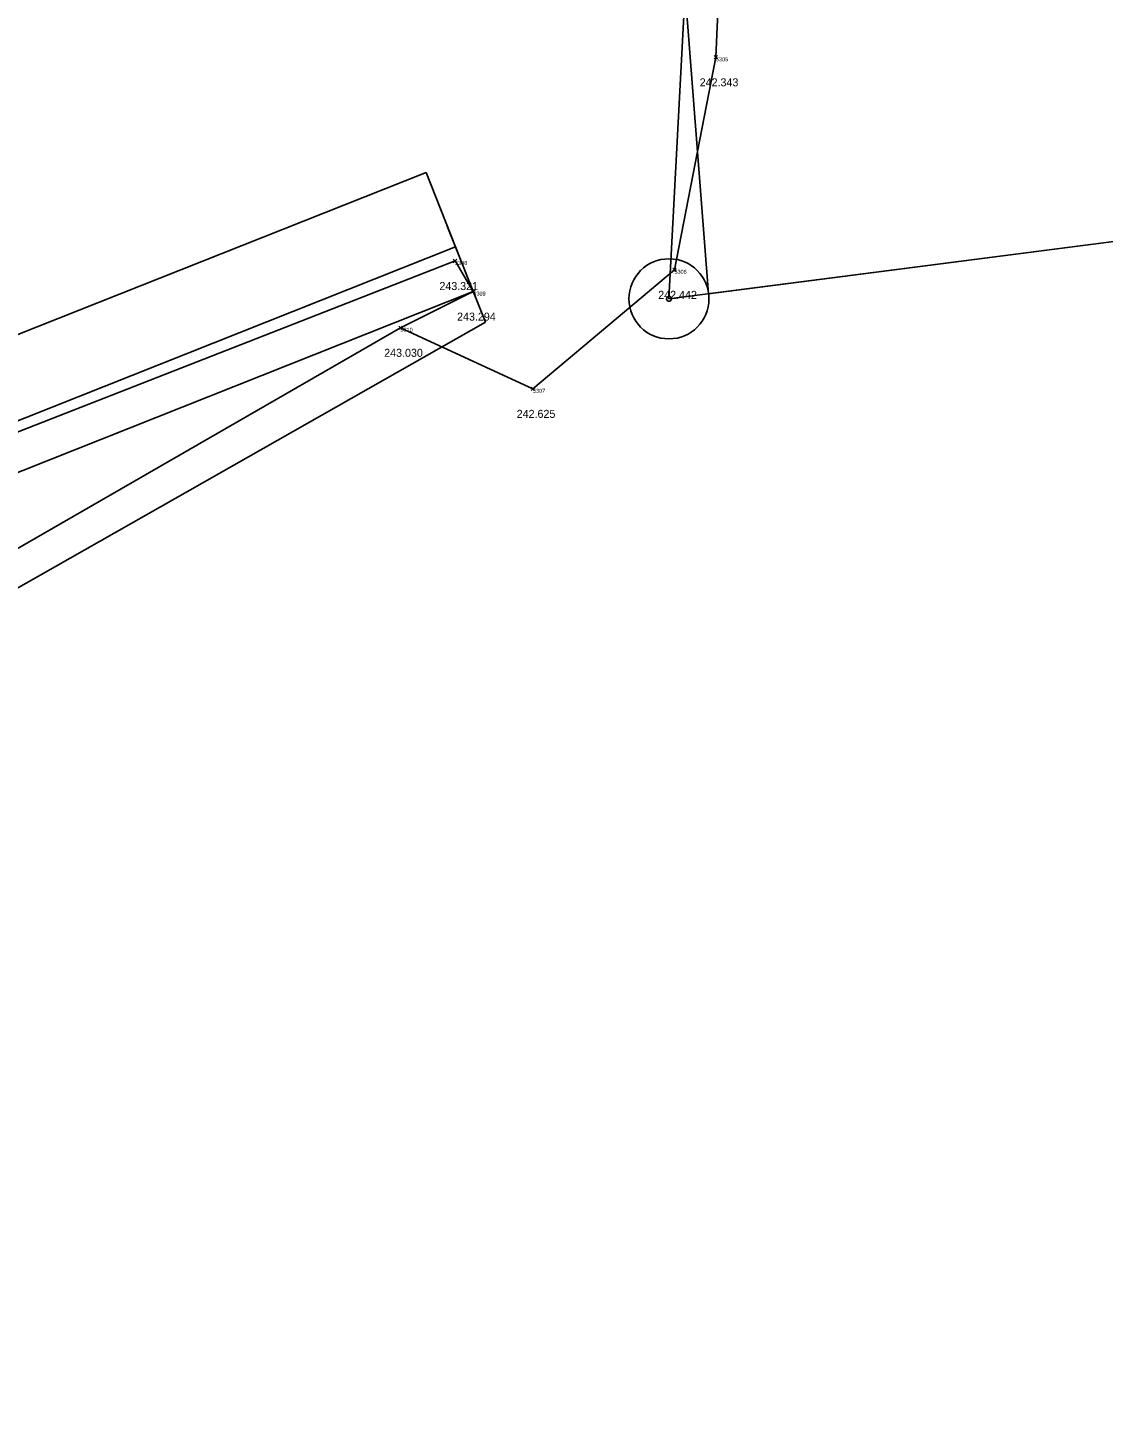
# Model space of a CAD drawing. Extents: x -809973 to -809318, y -1011363 to -1010505.
# Drawn here: x -809857.01 to -809843.56, y -1010848.32 to -1010831.13 of the extents above; entities that cross this region are included whole.
import ezdxf

# ---------------------------------------------------------------- set-up
doc = ezdxf.new("R2010")
doc.units = 0
for name, color, linetype in [('18b - zaměření - čísla bodů', 7, 'Continuous'), ('18c - zaměření - výšky', 7, 'Continuous'), ('19a - katastr hranice', 7, 'Continuous'), ('19b - katastr SŽDC', 7, 'Continuous'), ('26 - obvod_stavby', 7, 'Continuous'), ('SO_02', 7, 'Continuous'), ('stav_stav', 7, 'Continuous')]:
    doc.layers.add(name, color=color, linetype=linetype)

# ---------------------------------------------------------------- blocks, each defined once
blk = doc.blocks.new('POINT_DISPLAY')
for p, q in [((-0.021, -0.021), (0.021, 0.021)), ((-0.021, 0.021), (0.021, -0.021))]:
    blk.add_line(p, q)

msp = doc.modelspace()

# ---------------------------------------------------------------- linework, layer by layer
at = {"layer": '19a - katastr hranice'}
for radius in [0.5, 0.0303]:
    msp.add_circle((-809848.99, -1010834.52), radius, dxfattribs=at)
at = {"layer": '19b - katastr SŽDC'}
msp.add_lwpolyline([(-809854.75, -1010785.76), (-809847.8, -1010811.91), (-809848.47, -1010824.63), (-809848.99, -1010834.52), (-809828.94, -1010831.94), (-809811.76, -1010846.11), (-809806.99, -1010849.89), (-809798.33, -1010856.76), (-809803.49, -1010861.61), (-809820.27, -1010877.38), (-809819.54, -1010907.65), (-809817.34, -1010954.54), (-809819.55, -1010971.19), (-809826.87, -1010981.55), (-809825.08, -1010988.69), (-809823.59, -1010994.66), (-809817.83, -1011024.91), (-809805.06, -1011048.21), (-809777.13, -1011090.84), (-809773.31, -1011095.41), (-809752.3, -1011120.38), (-809722.41, -1011150.52), (-809685.06, -1011180.11)], dxfattribs=at)
at = {"layer": '26 - obvod_stavby'}
msp.add_lwpolyline([(-809819.539, -1010907.68), (-809820.27, -1010877.38), (-809829.436, -1010832.004), (-809848.494, -1010834.456), (-809851.275, -1010798.835), (-809898.47, -1010814.6), (-809894.78, -1010861.65), (-809893.92, -1010865.41), (-809890.33, -1010872.36), (-809883.983, -1010901.809), (-809870.58, -1010955.65), (-809864.77, -1010992.44), (-809850.32, -1011003.33), (-809836.26, -1011028.53), (-809823.575, -1011052.67), (-809819.672, -1011062.774), (-809810.213, -1011057.6)], dxfattribs=at)
at = {"layer": 'SO_02'}
for p, q in [((-809852.025, -1010832.942), (-809863.154, -1010837.357)), ((-809851.656, -1010833.871), (-809852.025, -1010832.942)), ((-809851.284, -1010834.811), (-809851.76, -1010833.611)), ((-809851.656, -1010833.871), (-809863.002, -1010838.373)), ((-809851.435, -1010834.429), (-809851.656, -1010833.871)), ((-809851.435, -1010834.429), (-809863.019, -1010839.025)), ((-809851.284, -1010834.811), (-809862.773, -1010841.34))]:
    msp.add_line(p, q, dxfattribs=at)
msp.add_lwpolyline([(-809851.664, -1010834.047), (-809851.435, -1010834.429), (-809852.346, -1010834.881), (-809862.853, -1010840.932), (-809862.84, -1010841.158), (-809862.938, -1010840.77)], dxfattribs=at)
at = {"layer": 'stav_stav'}
for p, q in [((-809848.403, -1010831.502), (-809848.228, -1010827.188)), ((-809848.922, -1010834.157), (-809848.403, -1010831.502)), ((-809863.109, -1010838.517), (-809851.664, -1010834.047)), ((-809863.109, -1010838.517), (-809851.664, -1010834.047)), ((-809851.664, -1010834.047), (-809851.435, -1010834.429)), ((-809851.664, -1010834.047), (-809851.435, -1010834.429)), ((-809850.69, -1010835.644), (-809848.922, -1010834.157)), ((-809851.435, -1010834.429), (-809863.019, -1010839.025)), ((-809851.435, -1010834.429), (-809852.346, -1010834.881)), ((-809851.435, -1010834.429), (-809852.346, -1010834.881)), ((-809852.346, -1010834.881), (-809862.853, -1010840.932)), ((-809852.346, -1010834.881), (-809850.69, -1010835.644))]:
    msp.add_line(p, q, dxfattribs=at)

# ---------------------------------------------------------------- block references
at = {"layer": '18b - zaměření - čísla bodů'}
for p in [(-809848.403, -1010831.502), (-809851.664, -1010834.047), (-809848.922, -1010834.157), (-809851.435, -1010834.429), (-809852.346, -1010834.881), (-809850.69, -1010835.644)]:
    msp.add_blockref('POINT_DISPLAY', p, dxfattribs=at)

# ---------------------------------------------------------------- texts
for s, p in [('5305', (-809848.403, -1010831.552)), ('5308', (-809851.664, -1010834.097)), ('5306', (-809848.922, -1010834.207)), ('5309', (-809851.435, -1010834.479)), ('5310', (-809852.346, -1010834.931)), ('5307', (-809850.69, -1010835.694))]:
    msp.add_text(s, height=0.05, dxfattribs=at).set_placement(p)
at = {"layer": '18c - zaměření - výšky'}
for s, p in [('242.343', (-809848.606, -1010831.865)), ('243.321', (-809851.859, -1010834.41)), ('242.442', (-809849.124, -1010834.52)), ('243.294', (-809851.638, -1010834.792)), ('243.030', (-809852.549, -1010835.244)), ('242.625', (-809850.893, -1010836.007))]:
    msp.add_text(s, height=0.1, dxfattribs=at).set_placement(p)

doc.saveas('drawing.dxf')
